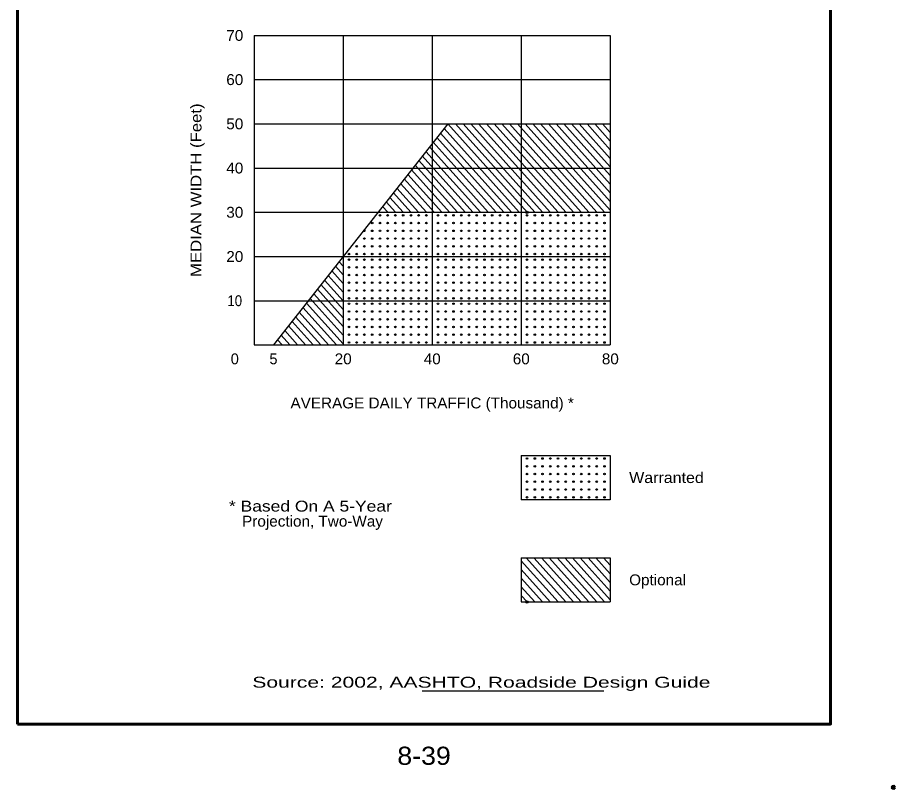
# Model space of a CAD drawing. Extents: x 58.027 to 58.702, y 1.635 to 2.519.
# Drawn here: x 58.073 to 58.702, y 1.635 to 2.189 of the extents above; entities that cross this region are included whole.
import ezdxf
from ezdxf.enums import TextEntityAlignment as Align

# ---------------------------------------------------------------- set-up
doc = ezdxf.new("R2010")
doc.units = 0
doc.header["$LTSCALE"] = 0.0031
doc.header["$PDMODE"] = 32
doc.header["$PDSIZE"] = 0.00155
doc.layers.add('1', color=7, linetype='Continuous', lineweight=60)
doc.layers.add('5', color=7, linetype='Continuous', lineweight=25)

msp = doc.modelspace()

# ---------------------------------------------------------------- linework, layer by layer
at = {"layer": '1'}
msp.add_line((58.072608, 1.68135), (58.072608, 2.472933), dxfattribs=at)
msp.add_lwpolyline([(58.655883, 2.472933), (58.655883, 1.68135), (58.072608, 1.68135)], dxfattribs=at)
msp.add_point((58.700942, 1.635933), dxfattribs=at)
at = {"layer": '5'}
for p, q in [((58.242317, 2.175767), (58.242317, 1.953567)), ((58.242317, 2.175767), (58.497842, 2.175767)), ((58.3062, 2.175767), (58.3062, 1.953567)), ((58.370083, 2.175767), (58.370083, 1.953567)), ((58.433967, 2.175767), (58.433967, 1.953567)), ((58.497842, 2.175767), (58.497842, 1.953567)), ((58.242317, 2.14405), (58.497842, 2.14405)), ((58.242317, 2.1123), (58.497842, 2.1123)), ((58.381192, 2.1123), (58.2562, 1.953567)), ((58.378592, 2.109), (58.432575, 2.048808)), ((58.381192, 2.1123), (58.438133, 2.048808)), ((58.381192, 2.1123), (58.497842, 2.1123)), ((58.386742, 2.1123), (58.443683, 2.048808)), ((58.3923, 2.1123), (58.449242, 2.048808)), ((58.397858, 2.1123), (58.454792, 2.048808)), ((58.403408, 2.1123), (58.46035, 2.048808)), ((58.408967, 2.1123), (58.465908, 2.048808)), ((58.414517, 2.1123), (58.471458, 2.048808)), ((58.420075, 2.1123), (58.477017, 2.048808)), ((58.425633, 2.1123), (58.482567, 2.048808)), ((58.431183, 2.1123), (58.488125, 2.048808)), ((58.436742, 2.1123), (58.493683, 2.048808)), ((58.442292, 2.1123), (58.497842, 2.050358)), ((58.44785, 2.1123), (58.497842, 2.05655)), ((58.453408, 2.1123), (58.497842, 2.06275)), ((58.458958, 2.1123), (58.497842, 2.068942)), ((58.464517, 2.1123), (58.497842, 2.075133)), ((58.470067, 2.1123), (58.497842, 2.081325)), ((58.475625, 2.1123), (58.497842, 2.087525)), ((58.481183, 2.1123), (58.497842, 2.093717)), ((58.486733, 2.1123), (58.497842, 2.099917)), ((58.492292, 2.1123), (58.497842, 2.106108)), ((58.3734, 2.102408), (58.421467, 2.048808)), ((58.376, 2.105708), (58.427017, 2.048808)), ((58.368208, 2.095808), (58.410358, 2.048808)), ((58.3708, 2.099108), (58.415908, 2.048808)), ((58.363008, 2.089217), (58.399242, 2.048808)), ((58.365608, 2.092508), (58.4048, 2.048808)), ((58.357817, 2.082617), (58.388133, 2.048808)), ((58.360417, 2.085917), (58.393692, 2.048808)), ((58.242317, 2.080558), (58.497842, 2.080558)), ((58.355217, 2.079317), (58.382583, 2.048808)), ((58.350025, 2.072725), (58.371467, 2.048808)), ((58.352625, 2.076017), (58.377025, 2.048808)), ((58.352625, 2.076017), (58.377025, 2.048808)), ((58.344833, 2.066125), (58.360358, 2.048808)), ((58.347425, 2.069425), (58.365917, 2.048808)), ((58.339633, 2.059525), (58.34925, 2.048808)), ((58.342233, 2.062825), (58.354808, 2.048808)), ((58.334442, 2.052933), (58.338142, 2.048808)), ((58.337042, 2.056233), (58.343692, 2.048808)), ((58.242317, 2.048808), (58.497842, 2.048808)), ((58.331842, 2.049633), (58.332583, 2.048808)), ((58.242317, 2.017058), (58.497842, 2.017058)), ((58.303275, 2.01335), (58.3062, 2.010092)), ((58.300683, 2.01005), (58.3062, 2.0039)), ((58.295483, 2.003458), (58.3062, 1.991508)), ((58.298083, 2.00675), (58.3062, 1.997708)), ((58.3062, 1.979125), (58.290292, 1.996858)), ((58.3062, 1.985317), (58.292892, 2.000158)), ((58.2851, 1.990258), (58.3062, 1.966733)), ((58.287692, 1.993558), (58.3062, 1.972925)), ((58.242317, 1.985317), (58.497842, 1.985317)), ((58.2799, 1.983667), (58.3062, 1.954342)), ((58.2825, 1.986967), (58.3062, 1.960542)), ((58.274708, 1.977067), (58.295783, 1.953567)), ((58.277308, 1.980367), (58.301342, 1.953567)), ((58.269517, 1.970475), (58.284675, 1.953567)), ((58.272108, 1.973767), (58.290225, 1.953567)), ((58.264317, 1.963875), (58.273567, 1.953567)), ((58.266917, 1.967175), (58.279117, 1.953567)), ((58.259125, 1.957283), (58.26245, 1.953567)), ((58.261725, 1.960575), (58.268008, 1.953567)), ((58.242317, 1.953567), (58.497842, 1.953567)), ((58.256525, 1.953983), (58.2569, 1.953567)), ((58.433967, 1.874217), (58.433967, 1.842467)), ((58.433967, 1.874217), (58.497842, 1.874217)), ((58.433967, 1.800808), (58.433967, 1.769058)), ((58.433967, 1.800808), (58.497842, 1.800808)), ((58.437433, 1.800808), (58.465908, 1.769058)), ((58.442992, 1.800808), (58.471458, 1.769058)), ((58.448542, 1.800808), (58.477017, 1.769058)), ((58.4541, 1.800808), (58.482567, 1.769058)), ((58.459658, 1.800808), (58.488125, 1.769058)), ((58.465208, 1.800808), (58.493683, 1.769058)), ((58.470767, 1.800808), (58.497842, 1.770608)), ((58.476317, 1.800808), (58.497842, 1.7768)), ((58.481875, 1.800808), (58.497842, 1.783)), ((58.487433, 1.800808), (58.497842, 1.789192)), ((58.492983, 1.800808), (58.497842, 1.795383)), ((58.497842, 1.800808), (58.497842, 1.769058)), ((58.433967, 1.798483), (58.46035, 1.769058)), ((58.433967, 1.792292), (58.454792, 1.769058)), ((58.433967, 1.786092), (58.449242, 1.769058)), ((58.433967, 1.7799), (58.443683, 1.769058)), ((58.433967, 1.773708), (58.438133, 1.769058)), ((58.433967, 1.769058), (58.497842, 1.769058)), ((58.362783, 1.705175), (58.493167, 1.705175))]:
    msp.add_line(p, q, dxfattribs=at)
msp.add_lwpolyline([(58.497842, 1.874217), (58.497842, 1.842467), (58.433967, 1.842467)], dxfattribs=at)
for centre in [(58.332584, 2.046614), (58.338139, 2.046614), (58.343694, 2.046614), (58.349249, 2.046614), (58.354804, 2.046614), (58.360359, 2.046614), (58.365914, 2.046614), (58.374247, 2.046614), (58.379802, 2.046614), (58.385357, 2.046614), (58.390912, 2.046614), (58.396467, 2.046614), (58.402022, 2.046614), (58.407577, 2.046614), (58.413132, 2.046614), (58.418687, 2.046614), (58.424242, 2.046614), (58.429797, 2.046614), (58.438129, 2.046614), (58.443684, 2.046614), (58.449239, 2.046614), (58.454794, 2.046614), (58.460349, 2.046614), (58.465904, 2.046614), (58.471459, 2.046614), (58.477014, 2.046614), (58.482569, 2.046614), (58.488124, 2.046614), (58.493679, 2.046614), (58.327029, 2.041059), (58.332584, 2.041059), (58.338139, 2.041059), (58.343694, 2.041059), (58.349249, 2.041059), (58.354804, 2.041059), (58.360359, 2.041059), (58.365914, 2.041059), (58.374247, 2.041059), (58.379802, 2.041059), (58.385357, 2.041059), (58.390912, 2.041059), (58.396467, 2.041059), (58.402022, 2.041059), (58.407577, 2.041059), (58.413132, 2.041059), (58.418687, 2.041059), (58.424242, 2.041059), (58.429797, 2.041059), (58.438129, 2.041059), (58.443684, 2.041059), (58.449239, 2.041059), (58.454794, 2.041059), (58.460349, 2.041059), (58.465904, 2.041059), (58.471459, 2.041059), (58.477014, 2.041059), (58.482569, 2.041059), (58.488124, 2.041059), (58.493679, 2.041059), (58.321474, 2.035504), (58.327029, 2.035504), (58.332584, 2.035504), (58.338139, 2.035504), (58.343694, 2.035504), (58.349249, 2.035504), (58.354804, 2.035504), (58.360359, 2.035504), (58.365914, 2.035504), (58.374247, 2.035504), (58.379802, 2.035504), (58.385357, 2.035504), (58.390912, 2.035504), (58.396467, 2.035504), (58.402022, 2.035504), (58.407577, 2.035504), (58.413132, 2.035504), (58.418687, 2.035504), (58.424242, 2.035504), (58.429797, 2.035504), (58.438129, 2.035504), (58.443684, 2.035504), (58.449239, 2.035504), (58.454794, 2.035504), (58.460349, 2.035504), (58.465904, 2.035504), (58.471459, 2.035504), (58.477014, 2.035504), (58.482569, 2.035504), (58.488124, 2.035504), (58.493679, 2.035504), (58.321474, 2.029949), (58.327029, 2.029949), (58.332584, 2.029949), (58.338139, 2.029949), (58.343694, 2.029949), (58.349249, 2.029949), (58.354804, 2.029949), (58.360359, 2.029949), (58.365914, 2.029949), (58.374247, 2.029949), (58.379802, 2.029949), (58.385357, 2.029949), (58.390912, 2.029949), (58.396467, 2.029949), (58.402022, 2.029949), (58.407577, 2.029949), (58.413132, 2.029949), (58.418687, 2.029949), (58.424242, 2.029949), (58.429797, 2.029949), (58.438129, 2.029949), (58.443684, 2.029949), (58.449239, 2.029949), (58.454794, 2.029949), (58.460349, 2.029949), (58.465904, 2.029949), (58.471459, 2.029949), (58.477014, 2.029949), (58.482569, 2.029949), (58.488124, 2.029949), (58.493679, 2.029949), (58.315919, 2.024394), (58.321474, 2.024394), (58.327029, 2.024394), (58.332584, 2.024394), (58.338139, 2.024394), (58.343694, 2.024394), (58.349249, 2.024394), (58.354804, 2.024394), (58.360359, 2.024394), (58.365914, 2.024394), (58.374247, 2.024394), (58.379802, 2.024394), (58.385357, 2.024394), (58.390912, 2.024394), (58.396467, 2.024394), (58.402022, 2.024394), (58.407577, 2.024394), (58.413132, 2.024394), (58.418687, 2.024394), (58.424242, 2.024394), (58.429797, 2.024394), (58.438129, 2.024394), (58.443684, 2.024394), (58.449239, 2.024394), (58.454794, 2.024394), (58.460349, 2.024394), (58.465904, 2.024394), (58.471459, 2.024394), (58.477014, 2.024394), (58.482569, 2.024394), (58.488124, 2.024394), (58.493679, 2.024394), (58.310364, 2.018839), (58.310364, 2.014867), (58.315919, 2.018839), (58.315919, 2.014867), (58.321474, 2.018839), (58.321474, 2.014867), (58.327029, 2.018839), (58.327029, 2.014867), (58.332584, 2.018839), (58.332584, 2.014867), (58.338139, 2.018839), (58.338139, 2.014867), (58.343694, 2.018839), (58.343694, 2.014867), (58.349249, 2.018839), (58.349249, 2.014867), (58.354804, 2.018839), (58.354804, 2.014867), (58.360359, 2.018839), (58.360359, 2.014867), (58.365914, 2.018839), (58.365914, 2.014867), (58.374247, 2.018839), (58.374247, 2.014867), (58.379802, 2.018839), (58.379802, 2.014867), (58.385357, 2.018839), (58.385357, 2.014867), (58.390912, 2.018839), (58.390912, 2.014867), (58.396467, 2.018839), (58.396467, 2.014867), (58.402022, 2.018839), (58.402022, 2.014867), (58.407577, 2.018839), (58.407577, 2.014867), (58.413132, 2.018839), (58.413132, 2.014867), (58.418687, 2.018839), (58.418687, 2.014867), (58.424242, 2.018839), (58.424242, 2.014867), (58.429797, 2.018839), (58.429797, 2.014867), (58.438129, 2.018839), (58.438129, 2.014867), (58.443684, 2.018839), (58.443684, 2.014867), (58.449239, 2.018839), (58.449239, 2.014867), (58.454794, 2.018839), (58.454794, 2.014867), (58.460349, 2.018839), (58.460349, 2.014867), (58.465904, 2.018839), (58.465904, 2.014867), (58.471459, 2.018839), (58.471459, 2.014867), (58.477014, 2.018839), (58.477014, 2.014867), (58.482569, 2.018839), (58.482569, 2.014867), (58.488124, 2.018839), (58.488124, 2.014867), (58.493679, 2.018839), (58.493679, 2.014867), (58.310364, 2.009312), (58.315919, 2.009312), (58.321474, 2.009312), (58.327029, 2.009312), (58.332584, 2.009312), (58.338139, 2.009312), (58.343694, 2.009312), (58.349249, 2.009312), (58.354804, 2.009312), (58.360359, 2.009312), (58.365914, 2.009312), (58.374247, 2.009312), (58.379802, 2.009312), (58.385357, 2.009312), (58.390912, 2.009312), (58.396467, 2.009312), (58.402022, 2.009312), (58.407577, 2.009312), (58.413132, 2.009312), (58.418687, 2.009312), (58.424242, 2.009312), (58.429797, 2.009312), (58.438129, 2.009312), (58.443684, 2.009312), (58.449239, 2.009312), (58.454794, 2.009312), (58.460349, 2.009312), (58.465904, 2.009312), (58.471459, 2.009312), (58.477014, 2.009312), (58.482569, 2.009312), (58.488124, 2.009312), (58.493679, 2.009312), (58.310364, 2.003757), (58.315919, 2.003757), (58.321474, 2.003757), (58.327029, 2.003757), (58.332584, 2.003757), (58.338139, 2.003757), (58.343694, 2.003757), (58.349249, 2.003757), (58.354804, 2.003757), (58.360359, 2.003757), (58.365914, 2.003757), (58.374247, 2.003757), (58.379802, 2.003757), (58.385357, 2.003757), (58.390912, 2.003757), (58.396467, 2.003757), (58.402022, 2.003757), (58.407577, 2.003757), (58.413132, 2.003757), (58.418687, 2.003757), (58.424242, 2.003757), (58.429797, 2.003757), (58.438129, 2.003757), (58.443684, 2.003757), (58.449239, 2.003757), (58.454794, 2.003757), (58.460349, 2.003757), (58.465904, 2.003757), (58.471459, 2.003757), (58.477014, 2.003757), (58.482569, 2.003757), (58.488124, 2.003757), (58.493679, 2.003757), (58.310364, 1.998202), (58.315919, 1.998202), (58.321474, 1.998202), (58.327029, 1.998202), (58.332584, 1.998202), (58.338139, 1.998202), (58.343694, 1.998202), (58.349249, 1.998202), (58.354804, 1.998202), (58.360359, 1.998202), (58.365914, 1.998202), (58.374247, 1.998202), (58.379802, 1.998202), (58.385357, 1.998202), (58.390912, 1.998202), (58.396467, 1.998202), (58.402022, 1.998202), (58.407577, 1.998202), (58.413132, 1.998202), (58.418687, 1.998202), (58.424242, 1.998202), (58.429797, 1.998202), (58.438129, 1.998202), (58.443684, 1.998202), (58.449239, 1.998202), (58.454794, 1.998202), (58.460349, 1.998202), (58.465904, 1.998202), (58.471459, 1.998202), (58.477014, 1.998202), (58.482569, 1.998202), (58.488124, 1.998202), (58.493679, 1.998202), (58.310364, 1.992647), (58.315919, 1.992647), (58.321474, 1.992647), (58.327029, 1.992647), (58.332584, 1.992647), (58.338139, 1.992647), (58.343694, 1.992647), (58.349249, 1.992647), (58.354804, 1.992647), (58.360359, 1.992647), (58.365914, 1.992647), (58.374247, 1.992647), (58.379802, 1.992647), (58.385357, 1.992647), (58.390912, 1.992647), (58.396467, 1.992647), (58.402022, 1.992647), (58.407577, 1.992647), (58.413132, 1.992647), (58.418687, 1.992647), (58.424242, 1.992647), (58.429797, 1.992647), (58.438129, 1.992647), (58.443684, 1.992647), (58.449239, 1.992647), (58.454794, 1.992647), (58.460349, 1.992647), (58.465904, 1.992647), (58.471459, 1.992647), (58.477014, 1.992647), (58.482569, 1.992647), (58.488124, 1.992647), (58.493679, 1.992647), (58.310364, 1.987092), (58.310364, 1.98312), (58.315919, 1.987092), (58.315919, 1.98312), (58.321474, 1.987092), (58.321474, 1.98312), (58.327029, 1.987092), (58.327029, 1.98312), (58.332584, 1.987092), (58.332584, 1.98312), (58.338139, 1.987092), (58.338139, 1.98312), (58.343694, 1.987092), (58.343694, 1.98312), (58.349249, 1.987092), (58.349249, 1.98312), (58.354804, 1.987092), (58.354804, 1.98312), (58.360359, 1.987092), (58.360359, 1.98312), (58.365914, 1.987092), (58.365914, 1.98312), (58.374247, 1.987092), (58.374247, 1.98312), (58.379802, 1.987092), (58.379802, 1.98312), (58.385357, 1.987092), (58.385357, 1.98312), (58.390912, 1.987092), (58.390912, 1.98312), (58.396467, 1.987092), (58.396467, 1.98312), (58.402022, 1.987092), (58.402022, 1.98312), (58.407577, 1.987092), (58.407577, 1.98312), (58.413132, 1.987092), (58.413132, 1.98312), (58.418687, 1.987092), (58.418687, 1.98312), (58.424242, 1.987092), (58.424242, 1.98312), (58.429797, 1.987092), (58.429797, 1.98312), (58.438129, 1.987092), (58.438129, 1.98312), (58.443684, 1.987092), (58.443684, 1.98312), (58.449239, 1.987092), (58.449239, 1.98312), (58.454794, 1.987092), (58.454794, 1.98312), (58.460349, 1.987092), (58.460349, 1.98312), (58.465904, 1.987092), (58.465904, 1.98312), (58.471459, 1.987092), (58.471459, 1.98312), (58.477014, 1.987092), (58.477014, 1.98312), (58.482569, 1.987092), (58.482569, 1.98312), (58.488124, 1.987092), (58.488124, 1.98312), (58.493679, 1.987092), (58.493679, 1.98312), (58.310364, 1.977565), (58.315919, 1.977565), (58.321474, 1.977565), (58.327029, 1.977565), (58.332584, 1.977565), (58.338139, 1.977565), (58.343694, 1.977565), (58.349249, 1.977565), (58.354804, 1.977565), (58.360359, 1.977565), (58.365914, 1.977565), (58.374247, 1.977565), (58.379802, 1.977565), (58.385357, 1.977565), (58.390912, 1.977565), (58.396467, 1.977565), (58.402022, 1.977565), (58.407577, 1.977565), (58.413132, 1.977565), (58.418687, 1.977565), (58.424242, 1.977565), (58.429797, 1.977565), (58.438129, 1.977565), (58.443684, 1.977565), (58.449239, 1.977565), (58.454794, 1.977565), (58.460349, 1.977565), (58.465904, 1.977565), (58.471459, 1.977565), (58.477014, 1.977565), (58.482569, 1.977565), (58.488124, 1.977565), (58.493679, 1.977565), (58.310364, 1.97201), (58.315919, 1.97201), (58.321474, 1.97201), (58.327029, 1.97201), (58.332584, 1.97201), (58.338139, 1.97201), (58.343694, 1.97201), (58.349249, 1.97201), (58.354804, 1.97201), (58.360359, 1.97201), (58.365914, 1.97201), (58.374247, 1.97201), (58.379802, 1.97201), (58.385357, 1.97201), (58.390912, 1.97201), (58.396467, 1.97201), (58.402022, 1.97201), (58.407577, 1.97201), (58.413132, 1.97201), (58.418687, 1.97201), (58.424242, 1.97201), (58.429797, 1.97201), (58.438129, 1.97201), (58.443684, 1.97201), (58.449239, 1.97201), (58.454794, 1.97201), (58.460349, 1.97201), (58.465904, 1.97201), (58.471459, 1.97201), (58.477014, 1.97201), (58.482569, 1.97201), (58.488124, 1.97201), (58.493679, 1.97201), (58.310364, 1.966455), (58.315919, 1.966455), (58.321474, 1.966455), (58.327029, 1.966455), (58.332584, 1.966455), (58.338139, 1.966455), (58.343694, 1.966455), (58.349249, 1.966455), (58.354804, 1.966455), (58.360359, 1.966455), (58.365914, 1.966455), (58.374247, 1.966455), (58.379802, 1.966455), (58.385357, 1.966455), (58.390912, 1.966455), (58.396467, 1.966455), (58.402022, 1.966455), (58.407577, 1.966455), (58.413132, 1.966455), (58.418687, 1.966455), (58.424242, 1.966455), (58.429797, 1.966455), (58.438129, 1.966455), (58.443684, 1.966455), (58.449239, 1.966455), (58.454794, 1.966455), (58.460349, 1.966455), (58.465904, 1.966455), (58.471459, 1.966455), (58.477014, 1.966455), (58.482569, 1.966455), (58.488124, 1.966455), (58.493679, 1.966455), (58.310364, 1.9609), (58.315919, 1.9609), (58.321474, 1.9609), (58.327029, 1.9609), (58.332584, 1.9609), (58.338139, 1.9609), (58.343694, 1.9609), (58.349249, 1.9609), (58.354804, 1.9609), (58.360359, 1.9609), (58.365914, 1.9609), (58.374247, 1.9609), (58.379802, 1.9609), (58.385357, 1.9609), (58.390912, 1.9609), (58.396467, 1.9609), (58.402022, 1.9609), (58.407577, 1.9609), (58.413132, 1.9609), (58.418687, 1.9609), (58.424242, 1.9609), (58.429797, 1.9609), (58.438129, 1.9609), (58.443684, 1.9609), (58.449239, 1.9609), (58.454794, 1.9609), (58.460349, 1.9609), (58.465904, 1.9609), (58.471459, 1.9609), (58.477014, 1.9609), (58.482569, 1.9609), (58.488124, 1.9609), (58.493679, 1.9609), (58.310364, 1.955345), (58.315919, 1.955345), (58.321474, 1.955345), (58.327029, 1.955345), (58.332584, 1.955345), (58.338139, 1.955345), (58.343694, 1.955345), (58.349249, 1.955345), (58.354804, 1.955345), (58.360359, 1.955345), (58.365914, 1.955345), (58.374247, 1.955345), (58.379802, 1.955345), (58.385357, 1.955345), (58.390912, 1.955345), (58.396467, 1.955345), (58.402022, 1.955345), (58.407577, 1.955345), (58.413132, 1.955345), (58.418687, 1.955345), (58.424242, 1.955345), (58.429797, 1.955345), (58.438129, 1.955345), (58.443684, 1.955345), (58.449239, 1.955345), (58.454794, 1.955345), (58.460349, 1.955345), (58.465904, 1.955345), (58.471459, 1.955345), (58.477014, 1.955345), (58.482569, 1.955345), (58.488124, 1.955345), (58.493679, 1.955345), (58.438129, 1.87202), (58.443684, 1.87202), (58.449239, 1.87202), (58.454794, 1.87202), (58.460349, 1.87202), (58.465904, 1.87202), (58.471459, 1.87202), (58.477014, 1.87202), (58.482569, 1.87202), (58.488124, 1.87202), (58.493679, 1.87202), (58.438129, 1.866465), (58.443684, 1.866465), (58.449239, 1.866465), (58.454794, 1.866465), (58.460349, 1.866465), (58.465904, 1.866465), (58.471459, 1.866465), (58.477014, 1.866465), (58.482569, 1.866465), (58.488124, 1.866465), (58.493679, 1.866465), (58.438129, 1.86091), (58.438129, 1.855355), (58.443684, 1.86091), (58.443684, 1.855355), (58.449239, 1.86091), (58.449239, 1.855355), (58.454794, 1.86091), (58.454794, 1.855355), (58.460349, 1.86091), (58.460349, 1.855355), (58.465904, 1.86091), (58.465904, 1.855355), (58.471459, 1.86091), (58.471459, 1.855355), (58.477014, 1.86091), (58.477014, 1.855355), (58.482569, 1.86091), (58.482569, 1.855355), (58.488124, 1.86091), (58.488124, 1.855355), (58.493679, 1.86091), (58.493679, 1.855355), (58.438129, 1.8498), (58.443684, 1.8498), (58.449239, 1.8498), (58.454794, 1.8498), (58.460349, 1.8498), (58.465904, 1.8498), (58.471459, 1.8498), (58.477014, 1.8498), (58.482569, 1.8498), (58.488124, 1.8498), (58.493679, 1.8498), (58.438129, 1.844245), (58.443684, 1.844245), (58.449239, 1.844245), (58.454794, 1.844245), (58.460349, 1.844245), (58.465904, 1.844245), (58.471459, 1.844245), (58.477014, 1.844245), (58.482569, 1.844245), (58.488124, 1.844245), (58.493679, 1.844245)]:
    msp.add_circle(centre, 0.000556, dxfattribs=at)
for p in [(58.438133, 2.048808), (58.438133, 1.769058)]:
    msp.add_point(p, dxfattribs=at)

# ---------------------------------------------------------------- texts
at = {"layer": '1'}
for s, height, width, p in [('70', 0.0078, 1.05, (58.228463, 2.171867)), ('60', 0.0078, 1.05, (58.228454, 2.14015)), ('50', 0.0078, 1.05, (58.228463, 2.1084)), ('40', 0.0078, 1.05, (58.228463, 2.076658)), ('30', 0.0078, 1.05, (58.228463, 2.044908)), ('20', 0.0078, 1.05, (58.228463, 2.013158)), ('10', 0.0078, 0.9, (58.228458, 1.981417)), ('20', 0.0078, 1.05, (58.306229, 1.939683)), ('40', 0.0078, 1.05, (58.370113, 1.939683)), ('60', 0.0078, 1.05, (58.433988, 1.939683)), ('80', 0.0078, 1.05, (58.497879, 1.939683)), ('AVERAGE DAILY TRAFFIC (Thousand) *', 0.0078, 1.05, (58.370079, 1.908008)), ('* Based On A 5-Year', 0.0078, 1.2, (58.282708, 1.833958)), (' Projection, Two-Way', 0.0078, 1.05, (58.282708, 1.823158)), ('Source: 2002, AASHTO, Roadside Design Guide', 0.0078, 1.45, (58.405375, 1.707533)), ('8-39', 0.01303, 1.1, (58.364246, 1.652125))]:
    msp.add_text(s, height=height, dxfattribs=dict(at, width=width)).set_placement(p, align=Align.CENTER)
at = {"layer": '1', "width": 1.15}
msp.add_text('MEDIAN WIDTH (Feet)', height=0.0078, rotation=90, dxfattribs=at).set_placement((58.20455, 2.064667), align=Align.CENTER)
at = {"layer": '1'}
for s, p in [('0', (58.228463, 1.939683)), ('5', (58.256208, 1.939683))]:
    msp.add_text(s, height=0.0078, dxfattribs=at).set_placement(p, align=Align.CENTER)
for s, width, p in [('Warranted', 1.1, (58.511383, 1.854442)), ('Optional', 1.05, (58.511383, 1.781033))]:
    msp.add_text(s, height=0.0078, dxfattribs=dict(at, width=width)).set_placement(p)

doc.saveas('drawing.dxf')
